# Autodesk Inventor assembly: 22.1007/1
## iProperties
Created: 2012-02
Part Number: 22.1007/1
Document SubType Name: Assembly
Designer: Administrator
Vendor: S
Description: END CAP 45X90 GRAY
Mass: 11.4345 g
Surface Area: 112.634 cm^2
Volume: 10.7873 cm^3
Density: 1.06 g/cm^3
Author: Administrator
